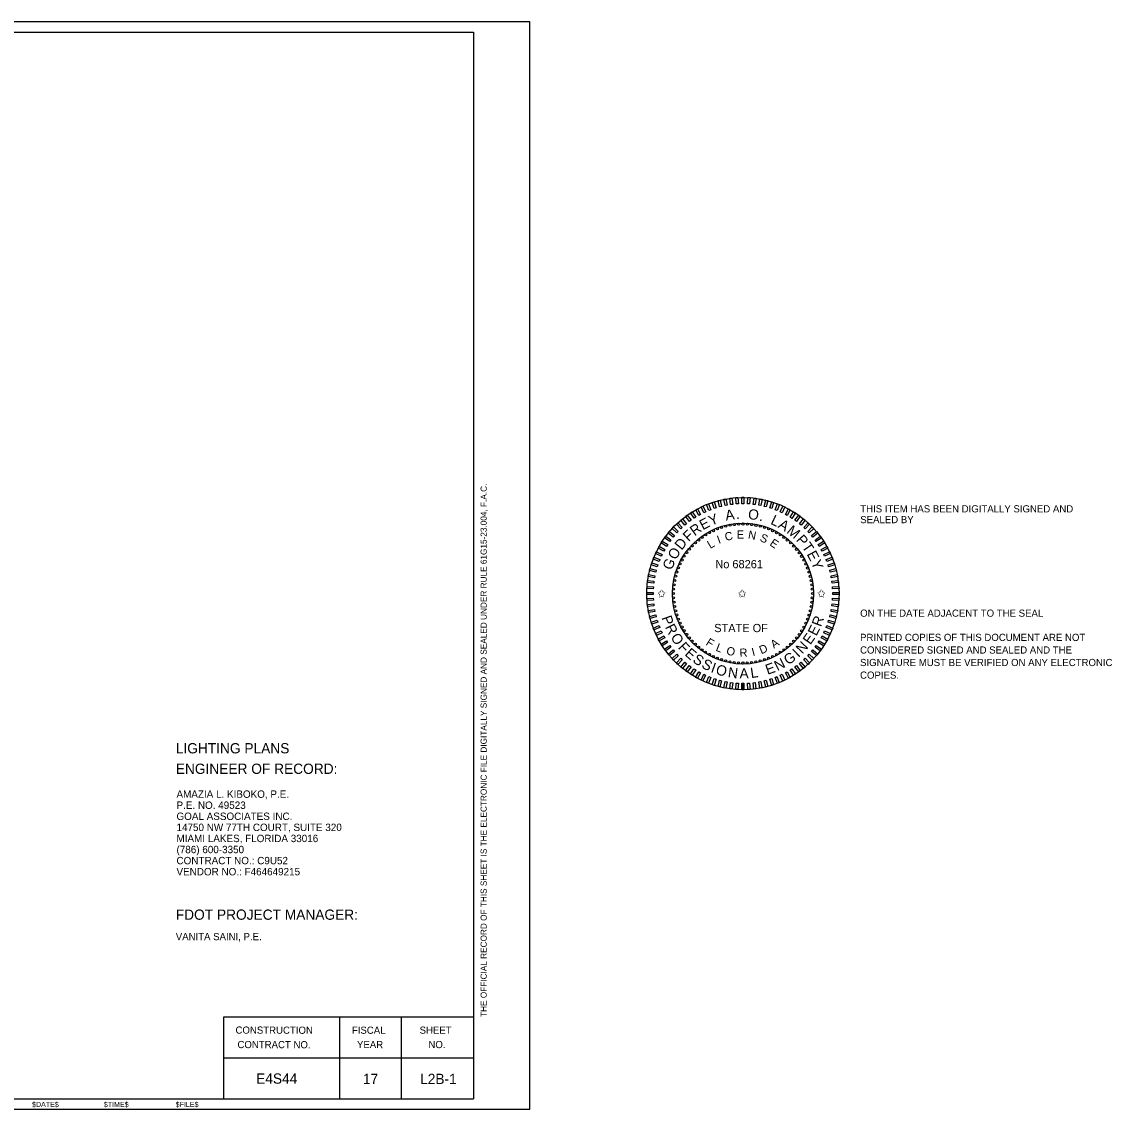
# Model space of a CAD drawing. Extents: x -820.2 to -798.1, y -2199.1 to -2188.5.
# Drawn here: x -808.68 to -798.05, y -2199.12 to -2188.52 of the extents above; entities that cross this region are included whole.
import ezdxf

# ---------------------------------------------------------------- set-up
doc = ezdxf.new("R2010")
doc.units = 0
for name, color, linetype in [('ActivePointCell_dp', 7, 'Continuous'), ('Logo_dp', 7, 'Continuous'), ('NonPlottingEle_dp', 7, 'Continuous'), ('PlotBorder_dp', 7, 'Continuous'), ('SheetBorder_dp', 7, 'Continuous'), ('SheetLines_dp', 7, 'Continuous'), ('TextLabel', 7, 'Continuous'), ('TextMinor', 7, 'Continuous'), ('TextMisc', 7, 'Continuous'), ('TextNotes', 7, 'Continuous'), ('TextShtNo', 7, 'Continuous')]:
    doc.layers.add(name, color=color, linetype=linetype)

msp = doc.modelspace()

# ---------------------------------------------------------------- linework, layer by layer
at = {"layer": 'ActivePointCell_dp'}
msp.add_line((-804.277, -2188.624), (-804.277, -2188.624), dxfattribs=at)
at = {"layer": 'Logo_dp'}
for p, q in [((-801.66, -2195.034), (-801.66, -2194.972)), ((-801.65, -2195.034), (-801.65, -2194.972)), ((-801.64, -2195.034), (-801.64, -2194.972))]:
    msp.add_line(p, q, dxfattribs=at)
for points in [[(-801.804, -2193.235), (-801.824, -2193.239), (-801.836, -2193.178), (-801.816, -2193.174)], [(-801.75, -2193.228), (-801.77, -2193.23), (-801.777, -2193.168), (-801.757, -2193.166)], [(-801.695, -2193.223), (-801.715, -2193.224), (-801.719, -2193.162), (-801.699, -2193.161)], [(-801.64, -2193.222), (-801.66, -2193.222), (-801.66, -2193.159), (-801.64, -2193.159)], [(-801.585, -2193.224), (-801.605, -2193.223), (-801.601, -2193.161), (-801.581, -2193.162)], [(-801.53, -2193.23), (-801.55, -2193.228), (-801.542, -2193.166), (-801.522, -2193.168)], [(-801.476, -2193.239), (-801.496, -2193.236), (-801.484, -2193.174), (-801.464, -2193.178)], [(-802.063, -2193.325), (-802.08, -2193.335), (-802.11, -2193.28), (-802.093, -2193.271)], [(-802.013, -2193.301), (-802.032, -2193.309), (-802.058, -2193.253), (-802.04, -2193.244)], [(-801.963, -2193.28), (-801.981, -2193.287), (-802.004, -2193.229), (-801.986, -2193.222)], [(-801.911, -2193.262), (-801.93, -2193.268), (-801.949, -2193.208), (-801.93, -2193.202)], [(-801.858, -2193.247), (-801.877, -2193.252), (-801.893, -2193.191), (-801.873, -2193.186)], [(-801.423, -2193.252), (-801.442, -2193.247), (-801.427, -2193.186), (-801.407, -2193.191)], [(-801.37, -2193.268), (-801.389, -2193.262), (-801.37, -2193.202), (-801.351, -2193.208)], [(-801.318, -2193.287), (-801.337, -2193.28), (-801.314, -2193.222), (-801.295, -2193.229)], [(-801.268, -2193.31), (-801.287, -2193.301), (-801.26, -2193.244), (-801.242, -2193.253)], [(-801.22, -2193.335), (-801.237, -2193.325), (-801.207, -2193.271), (-801.19, -2193.28)], [(-802.2, -2193.416), (-802.216, -2193.429), (-802.255, -2193.381), (-802.24, -2193.368)], [(-802.156, -2193.383), (-802.172, -2193.395), (-802.209, -2193.344), (-802.193, -2193.333)], [(-802.11, -2193.353), (-802.127, -2193.363), (-802.161, -2193.311), (-802.144, -2193.3)], [(-801.173, -2193.364), (-801.19, -2193.353), (-801.156, -2193.3), (-801.139, -2193.311)], [(-801.127, -2193.395), (-801.144, -2193.383), (-801.107, -2193.333), (-801.091, -2193.344)], [(-801.084, -2193.429), (-801.1, -2193.416), (-801.06, -2193.368), (-801.045, -2193.381)], [(-802.318, -2193.531), (-802.331, -2193.547), (-802.379, -2193.507), (-802.366, -2193.492)], [(-802.281, -2193.491), (-802.295, -2193.505), (-802.34, -2193.462), (-802.326, -2193.448)], [(-802.242, -2193.452), (-802.256, -2193.466), (-802.299, -2193.42), (-802.284, -2193.407)], [(-801.044, -2193.466), (-801.058, -2193.452), (-801.016, -2193.407), (-801.001, -2193.421)], [(-801.005, -2193.505), (-801.019, -2193.491), (-800.974, -2193.448), (-800.96, -2193.463)], [(-800.969, -2193.547), (-800.982, -2193.531), (-800.934, -2193.492), (-800.921, -2193.507)], [(-802.383, -2193.619), (-802.394, -2193.637), (-802.447, -2193.603), (-802.436, -2193.586)], [(-802.352, -2193.574), (-802.364, -2193.591), (-802.414, -2193.554), (-802.403, -2193.538)], [(-800.936, -2193.591), (-800.948, -2193.575), (-800.898, -2193.538), (-800.886, -2193.554)], [(-800.906, -2193.637), (-800.917, -2193.62), (-800.864, -2193.586), (-800.853, -2193.603)], [(-802.437, -2193.715), (-802.446, -2193.733), (-802.503, -2193.707), (-802.494, -2193.689)], [(-802.412, -2193.666), (-802.422, -2193.684), (-802.476, -2193.654), (-802.467, -2193.636)], [(-800.878, -2193.684), (-800.888, -2193.667), (-800.833, -2193.637), (-800.824, -2193.654)], [(-800.854, -2193.734), (-800.863, -2193.715), (-800.806, -2193.689), (-800.797, -2193.707)], [(-802.479, -2193.817), (-802.485, -2193.836), (-802.545, -2193.817), (-802.539, -2193.798)], [(-802.46, -2193.765), (-802.467, -2193.784), (-802.525, -2193.761), (-802.518, -2193.742)], [(-800.833, -2193.784), (-800.84, -2193.766), (-800.782, -2193.743), (-800.775, -2193.761)], [(-800.815, -2193.836), (-800.821, -2193.817), (-800.762, -2193.798), (-800.755, -2193.817)], [(-802.508, -2193.923), (-802.511, -2193.943), (-802.573, -2193.931), (-802.569, -2193.911)], [(-802.495, -2193.869), (-802.5, -2193.889), (-802.561, -2193.873), (-802.556, -2193.854)], [(-800.8, -2193.889), (-800.805, -2193.87), (-800.745, -2193.854), (-800.74, -2193.874)], [(-800.789, -2193.943), (-800.792, -2193.923), (-800.731, -2193.911), (-800.727, -2193.931)], [(-802.523, -2194.032), (-802.524, -2194.052), (-802.586, -2194.048), (-802.585, -2194.028)], [(-802.517, -2193.977), (-802.519, -2193.997), (-802.581, -2193.989), (-802.579, -2193.969)], [(-800.781, -2193.997), (-800.783, -2193.977), (-800.721, -2193.97), (-800.719, -2193.99)], [(-800.776, -2194.052), (-800.777, -2194.032), (-800.715, -2194.028), (-800.714, -2194.048)], [(-802.525, -2194.087), (-802.525, -2194.107), (-802.588, -2194.107), (-802.588, -2194.087)], [(-800.775, -2194.107), (-800.775, -2194.087), (-800.713, -2194.087), (-800.713, -2194.107)], [(-802.524, -2194.142), (-802.523, -2194.162), (-802.585, -2194.166), (-802.586, -2194.146)], [(-802.519, -2194.196), (-802.517, -2194.217), (-802.579, -2194.224), (-802.581, -2194.204)], [(-800.783, -2194.217), (-800.781, -2194.197), (-800.719, -2194.205), (-800.721, -2194.225)], [(-800.777, -2194.162), (-800.776, -2194.142), (-800.714, -2194.146), (-800.715, -2194.166)], [(-802.512, -2194.251), (-802.508, -2194.271), (-802.569, -2194.282), (-802.573, -2194.263)], [(-802.5, -2194.305), (-802.495, -2194.324), (-802.556, -2194.34), (-802.561, -2194.32)], [(-800.805, -2194.324), (-800.8, -2194.305), (-800.74, -2194.32), (-800.745, -2194.34)], [(-800.792, -2194.271), (-800.789, -2194.251), (-800.727, -2194.263), (-800.731, -2194.283)], [(-802.485, -2194.358), (-802.479, -2194.377), (-802.539, -2194.396), (-802.545, -2194.377)], [(-802.467, -2194.41), (-802.46, -2194.428), (-802.518, -2194.451), (-802.525, -2194.433)], [(-800.84, -2194.429), (-800.833, -2194.41), (-800.775, -2194.433), (-800.782, -2194.452)], [(-800.821, -2194.377), (-800.815, -2194.358), (-800.755, -2194.377), (-800.762, -2194.396)], [(-802.446, -2194.46), (-802.438, -2194.479), (-802.494, -2194.505), (-802.503, -2194.487)], [(-802.422, -2194.51), (-802.412, -2194.527), (-802.467, -2194.557), (-802.476, -2194.54)], [(-802.394, -2194.557), (-802.384, -2194.574), (-802.436, -2194.608), (-802.447, -2194.591)], [(-800.917, -2194.574), (-800.906, -2194.557), (-800.853, -2194.591), (-800.864, -2194.608)], [(-800.888, -2194.527), (-800.878, -2194.51), (-800.824, -2194.54), (-800.833, -2194.557)], [(-800.863, -2194.479), (-800.854, -2194.46), (-800.798, -2194.487), (-800.806, -2194.505)], [(-802.364, -2194.603), (-802.352, -2194.619), (-802.403, -2194.656), (-802.414, -2194.64)], [(-802.331, -2194.647), (-802.318, -2194.662), (-802.366, -2194.702), (-802.379, -2194.687)], [(-800.982, -2194.663), (-800.969, -2194.647), (-800.921, -2194.687), (-800.934, -2194.702)], [(-800.948, -2194.619), (-800.936, -2194.603), (-800.886, -2194.64), (-800.898, -2194.656)], [(-802.295, -2194.688), (-802.281, -2194.703), (-802.327, -2194.746), (-802.34, -2194.731)], [(-802.256, -2194.728), (-802.242, -2194.742), (-802.285, -2194.787), (-802.299, -2194.773)], [(-802.216, -2194.765), (-802.2, -2194.778), (-802.24, -2194.826), (-802.255, -2194.813)], [(-801.1, -2194.778), (-801.085, -2194.765), (-801.045, -2194.813), (-801.06, -2194.826)], [(-801.058, -2194.742), (-801.044, -2194.728), (-801.001, -2194.773), (-801.016, -2194.787)], [(-801.019, -2194.703), (-801.005, -2194.689), (-800.96, -2194.731), (-800.974, -2194.746)], [(-802.173, -2194.799), (-802.156, -2194.811), (-802.193, -2194.861), (-802.209, -2194.849)], [(-802.128, -2194.83), (-802.11, -2194.841), (-802.144, -2194.894), (-802.161, -2194.883)], [(-802.081, -2194.859), (-802.063, -2194.869), (-802.093, -2194.923), (-802.111, -2194.914)], [(-801.237, -2194.869), (-801.22, -2194.859), (-801.19, -2194.914), (-801.207, -2194.923)], [(-801.19, -2194.841), (-801.173, -2194.83), (-801.139, -2194.883), (-801.156, -2194.894)], [(-801.144, -2194.811), (-801.128, -2194.799), (-801.091, -2194.849), (-801.107, -2194.861)], [(-802.032, -2194.884), (-802.014, -2194.893), (-802.04, -2194.949), (-802.058, -2194.941)], [(-801.982, -2194.907), (-801.963, -2194.914), (-801.986, -2194.972), (-802.005, -2194.965)], [(-801.93, -2194.926), (-801.911, -2194.932), (-801.93, -2194.992), (-801.949, -2194.985)], [(-801.878, -2194.942), (-801.858, -2194.947), (-801.874, -2195.007), (-801.893, -2195.002)], [(-801.824, -2194.955), (-801.804, -2194.958), (-801.816, -2195.02), (-801.836, -2195.016)], [(-801.77, -2194.964), (-801.75, -2194.966), (-801.758, -2195.028), (-801.778, -2195.026)], [(-801.715, -2194.97), (-801.695, -2194.971), (-801.699, -2195.033), (-801.719, -2195.032)], [(-801.66, -2194.972), (-801.64, -2194.972), (-801.64, -2195.034), (-801.66, -2195.034)], [(-801.605, -2194.971), (-801.585, -2194.97), (-801.581, -2195.032), (-801.601, -2195.033)], [(-801.551, -2194.966), (-801.53, -2194.964), (-801.523, -2195.026), (-801.543, -2195.028)], [(-801.496, -2194.958), (-801.476, -2194.955), (-801.465, -2195.016), (-801.484, -2195.02)], [(-801.442, -2194.947), (-801.423, -2194.942), (-801.407, -2195.002), (-801.427, -2195.007)], [(-801.389, -2194.932), (-801.37, -2194.926), (-801.351, -2194.985), (-801.37, -2194.992)], [(-801.337, -2194.914), (-801.319, -2194.907), (-801.296, -2194.965), (-801.314, -2194.972)], [(-801.287, -2194.893), (-801.268, -2194.884), (-801.242, -2194.941), (-801.26, -2194.95)]]:
    msp.add_lwpolyline(points, close=True, dxfattribs=at)
for centre in [(-801.976, -2193.503), (-801.938, -2193.484), (-801.899, -2193.467), (-801.859, -2193.452), (-801.818, -2193.441), (-801.776, -2193.431), (-801.734, -2193.425), (-801.692, -2193.421), (-801.65, -2193.419), (-801.607, -2193.421), (-801.565, -2193.425), (-801.523, -2193.432), (-801.481, -2193.441), (-801.44, -2193.453), (-801.4, -2193.467), (-801.361, -2193.484), (-801.323, -2193.504), (-802.113, -2193.603), (-802.081, -2193.575), (-802.048, -2193.549), (-802.013, -2193.525), (-801.287, -2193.525), (-801.251, -2193.549), (-801.218, -2193.575), (-801.186, -2193.603), (-802.198, -2193.698), (-802.172, -2193.665), (-802.144, -2193.633), (-801.156, -2193.634), (-801.128, -2193.666), (-801.102, -2193.699), (-802.263, -2193.808), (-802.243, -2193.77), (-802.222, -2193.733), (-801.078, -2193.734), (-801.056, -2193.771), (-801.037, -2193.809), (-802.306, -2193.928), (-802.294, -2193.887), (-802.28, -2193.847), (-801.02, -2193.848), (-801.006, -2193.888), (-800.994, -2193.929), (-802.322, -2194.011), (-802.315, -2193.969), (-800.984, -2193.971), (-800.978, -2194.013), (-802.328, -2194.096), (-802.326, -2194.054), (-802.326, -2194.139), (-800.974, -2194.055), (-800.974, -2194.14), (-800.973, -2194.097), (-802.322, -2194.181), (-802.316, -2194.223), (-800.985, -2194.224), (-800.978, -2194.182), (-802.306, -2194.265), (-802.295, -2194.306), (-802.28, -2194.346), (-801.02, -2194.347), (-801.006, -2194.307), (-800.994, -2194.266), (-802.263, -2194.385), (-802.244, -2194.423), (-802.222, -2194.459), (-801.078, -2194.46), (-801.057, -2194.424), (-801.037, -2194.386), (-802.198, -2194.495), (-802.172, -2194.528), (-802.144, -2194.56), (-801.157, -2194.561), (-801.128, -2194.529), (-801.102, -2194.496), (-802.114, -2194.59), (-802.082, -2194.619), (-802.049, -2194.645), (-802.014, -2194.669), (-801.288, -2194.669), (-801.252, -2194.645), (-801.219, -2194.619), (-801.187, -2194.591), (-801.977, -2194.69), (-801.939, -2194.71), (-801.9, -2194.727), (-801.86, -2194.741), (-801.819, -2194.753), (-801.778, -2194.762), (-801.736, -2194.769), (-801.693, -2194.773), (-801.65, -2194.774), (-801.608, -2194.773), (-801.566, -2194.769), (-801.524, -2194.762), (-801.482, -2194.753), (-801.441, -2194.741), (-801.401, -2194.727), (-801.362, -2194.71), (-801.324, -2194.691)]:
    msp.add_circle(centre, 0.01, dxfattribs=at)
at = {"layer": 'NonPlottingEle_dp'}
for radius in [0.937, 0.687]:
    msp.add_circle((-801.65, -2194.097), radius, dxfattribs=at)
at = {"layer": 'PlotBorder_dp'}
msp.add_lwpolyline([(-820.227, -2199.124), (-803.727, -2199.124), (-803.727, -2188.524), (-820.227, -2188.524)], close=True, dxfattribs=at)
at = {"layer": 'SheetBorder_dp'}
for p, q in [((-819.677, -2188.624), (-804.277, -2188.624)), ((-804.277, -2188.624), (-804.277, -2199.024)), ((-819.677, -2199.024), (-804.277, -2199.024))]:
    msp.add_line(p, q, dxfattribs=at)
at = {"layer": 'SheetLines_dp'}
for p, q in [((-806.708, -2198.224), (-804.277, -2198.224)), ((-806.708, -2199.024), (-806.708, -2198.224)), ((-805.577, -2199.024), (-805.577, -2198.224)), ((-804.977, -2199.024), (-804.977, -2198.224)), ((-806.708, -2198.624), (-804.277, -2198.624))]:
    msp.add_line(p, q, dxfattribs=at)

# ---------------------------------------------------------------- texts
at = {"layer": 'Logo_dp'}
for s, height, rotation, p in [('A', 0.1, 8.8088, (-801.815, -2193.386)), ('O', 0.1, 352.1877, (-801.605, -2193.369)), ('E', 0.1, 28.1055, (-802.041, -2193.481)), ('Y', 0.1, 21.0633, (-801.962, -2193.438)), ('.', 0.1, 1.0418, (-801.717, -2193.371)), ('.', 0.1, 343.5268, (-801.496, -2193.384)), ('L', 0.1, 334.6727, (-801.388, -2193.416)), ('A', 0.1, 328.4096, (-801.315, -2193.449)), ('F', 0.1, 42.3772, (-802.18, -2193.596)), ('R', 0.1, 35.9269, (-802.121, -2193.54)), ('C', 0.08, 12.2025, (-801.818, -2193.585)), ('E', 0.08, 0.4186, (-801.71, -2193.562)), ('N', 0.08, 349.2914, (-801.605, -2193.56)), ('M', 0.1, 320.6426, (-801.231, -2193.5)), ('D', 0.1, 50.8569, (-802.248, -2193.68)), ('L', 0.08, 30.4021, (-801.969, -2193.663)), ('I', 0.08, 20.0117, (-801.886, -2193.613)), ('S', 0.08, 337.0221, (-801.492, -2193.582)), ('E', 0.08, 325.8663, (-801.396, -2193.622)), ('P', 0.1, 311.1966, (-801.138, -2193.577)), ('T', 0.1, 304.4563, (-801.081, -2193.641)), ('O', 0.1, 59.5178, (-802.304, -2193.775)), ('E', 0.1, 297.6315, (-801.031, -2193.712)), ('G', 0.1, 68.0518, (-802.345, -2193.875)), ('Y', 0.1, 290.5893, (-800.988, -2193.79)), ('P', 0.1, 289.4055, (-802.445, -2194.332)), ('R', 0.1, 69.5134, (-800.89, -2194.427)), ('R', 0.1, 296.1458, (-802.412, -2194.423)), ('E', 0.1, 62.4712, (-800.936, -2194.517)), ('O', 0.1, 303.9671, (-802.36, -2194.524)), ('F', 0.08, 328.7241, (-802.018, -2194.594)), ('A', 0.08, 34.4992, (-801.348, -2194.636)), ('N', 0.1, 47.1788, (-801.072, -2194.691)), ('E', 0.1, 55.4289, (-800.993, -2194.602)), ('F', 0.1, 312.628, (-802.288, -2194.626)), ('E', 0.1, 319.0783, (-802.224, -2194.694)), ('L', 0.08, 339.2916, (-801.921, -2194.653)), ('O', 0.08, 349.6821, (-801.816, -2194.692)), ('R', 0.08, 2.3398, (-801.682, -2194.714)), ('I', 0.08, 14.2037, (-801.554, -2194.708)), ('D', 0.08, 22.0128, (-801.472, -2194.689)), ('I', 0.1, 43.6456, (-801.11, -2194.725)), ('S', 0.1, 326.1206, (-802.147, -2194.76)), ('S', 0.1, 333.193, (-802.061, -2194.816)), ('I', 0.1, 340.2654, (-801.97, -2194.861)), ('E', 0.1, 19.8191, (-801.41, -2194.89)), ('N', 0.1, 26.8614, (-801.314, -2194.854)), ('G', 0.1, 35.1115, (-801.209, -2194.798)), ('O', 0.1, 343.7986, (-801.922, -2194.88)), ('N', 0.1, 352.4595, (-801.801, -2194.912)), ('A', 0.1, 0.7097, (-801.683, -2194.925)), ('L', 0.1, 8.4767, (-801.57, -2194.922))]:
    msp.add_text(s, height=height, rotation=rotation, dxfattribs=at).set_placement(p)
for s, p in [('No 68261', (-801.919, -2193.85)), ('✩', (-802.485, -2194.135)), ('✩', (-801.7, -2194.135)), ('✩', (-800.928, -2194.135)), ('STATE OF', (-801.93, -2194.473))]:
    msp.add_text(s, height=0.08, dxfattribs=at).set_placement(p)
at = {"layer": 'TextLabel'}
for s, height, p in [('LIGHTING PLANS', 0.1, (-807.177, -2195.655)), ('ENGINEER OF RECORD:', 0.1, (-807.177, -2195.855)), ('AMAZIA L. KIBOKO, P.E.', 0.07202, (-807.17, -2196.088)), ('P.E. NO. 49523', 0.07202, (-807.17, -2196.196)), ('GOAL ASSOCIATES INC. ', 0.07202, (-807.17, -2196.304)), ('14750 NW 77TH COURT, SUITE 320', 0.07202, (-807.17, -2196.412)), ('MIAMI LAKES, FLORIDA 33016', 0.07202, (-807.17, -2196.52)), ('(786) 600-3350', 0.07202, (-807.17, -2196.628)), ('CONTRACT NO.: C9U52', 0.07202, (-807.17, -2196.736)), ('VENDOR NO.: F464649215', 0.07202, (-807.17, -2196.844)), ('E4S44', 0.1, (-806.394, -2198.875))]:
    msp.add_text(s, height=height, dxfattribs=at).set_placement(p)
at = {"layer": 'TextMinor'}
for s, p in [('$DATE$', (-808.578, -2199.102)), ('$TIME$', (-807.878, -2199.102)), ('$FILE$', (-807.178, -2199.102))]:
    msp.add_text(s, height=0.05, rotation=360, dxfattribs=at).set_placement(p)
at = {"layer": 'TextMisc'}
msp.add_text('THE OFFICIAL RECORD OF THIS SHEET IS THE ELECTRONIC FILE DIGITALLY SIGNED AND SEALED UNDER RULE 61G15-23.004, F.A.C.', height=0.06, rotation=90, dxfattribs=at).set_placement((-804.147, -2198.224))
for s, p in [('THIS ITEM HAS BEEN DIGITALLY SIGNED AND ', (-800.507, -2193.306)), ('SEALED BY', (-800.507, -2193.411)), ('ON THE DATE ADJACENT TO THE SEAL', (-800.508, -2194.323)), ('PRINTED COPIES OF THIS DOCUMENT ARE NOT ', (-800.509, -2194.559)), ('CONSIDERED SIGNED AND SEALED AND THE ', (-800.509, -2194.682)), ('SIGNATURE MUST BE VERIFIED ON ANY ELECTRONIC ', (-800.509, -2194.804)), ('COPIES.', (-800.509, -2194.927))]:
    msp.add_text(s, height=0.07, dxfattribs=at).set_placement(p)
at = {"layer": 'TextNotes'}
for s, height, p in [('FDOT PROJECT MANAGER:', 0.1, (-807.177, -2197.277)), ('VANITA SAINI, P.E.', 0.07, (-807.177, -2197.476))]:
    msp.add_text(s, height=height, dxfattribs=at).set_placement(p)
for s, p in [('CONSTRUCTION', (-806.595, -2198.387)), ('FISCAL', (-805.461, -2198.388)), ('SHEET', (-804.801, -2198.388)), ('CONTRACT NO.', (-806.576, -2198.528)), ('YEAR', (-805.411, -2198.528)), ('NO.', (-804.715, -2198.528))]:
    msp.add_text(s, height=0.07, rotation=359.8607, dxfattribs=at).set_placement(p)
at = {"layer": 'TextShtNo'}
for s, p in [('17', (-805.354, -2198.878)), ('L2B-1', (-804.796, -2198.878))]:
    msp.add_text(s, height=0.1, dxfattribs=at).set_placement(p)

doc.saveas('drawing.dxf')
